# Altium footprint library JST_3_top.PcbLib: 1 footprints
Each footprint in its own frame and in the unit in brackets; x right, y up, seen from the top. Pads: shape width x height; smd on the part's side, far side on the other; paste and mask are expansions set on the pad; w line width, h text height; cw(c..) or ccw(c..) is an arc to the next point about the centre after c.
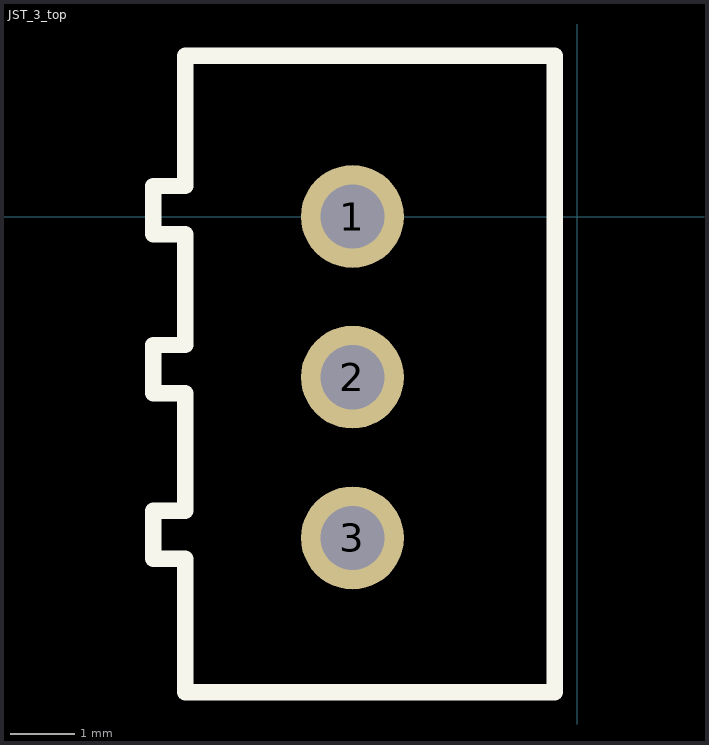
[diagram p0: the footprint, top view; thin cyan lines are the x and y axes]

## JST_3_top [mm]
pads (3):
  round 1.6 hole 1: 1(-3.5,0) 2(-3.5,-2.5) 3(-3.5,-5)
Top Overlay:
  lines w0.254: -6.6,-5.325 -6.6,-4.575 -6.1,-4.575 -6.1,-2.75 -6.6,-2.75 -6.6,-2 -6.1,-2 -6.1,-0.275 -6.6,-0.275 -6.6,0.475 -6.1,0.475 -6.1,2.5 -0.35,2.5 -0.35,-7.4 -6.1,-7.4 -6.1,-5.325 -6.6,-5.325
3D body: height 7, standoff 0, extent -6.727,-7.527 -0.223,2.627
